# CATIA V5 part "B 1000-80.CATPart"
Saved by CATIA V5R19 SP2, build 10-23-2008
Part number: B 1000-80
Bounding box of the stored display mesh (mm): x -24.865 to 24.865, y -24.997 to 24.997, z 0 to 255
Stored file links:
  C:\Users\Bora\Desktop\3D Katı model\B serisi\B 1000\B 1000-80.CATPart
  C:\Program Files\Dassault Systemes\B19\intel_a\reffiles\standard\MetricThickPitch.txt
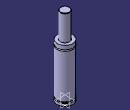
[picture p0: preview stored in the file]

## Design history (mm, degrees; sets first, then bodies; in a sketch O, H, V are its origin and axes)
Body1 (main body)
  Sketch1 on yz-plane, origin (0, 0, 0), H (0, 1, 0), V (0, 0, 1)
    point P1 (25, 159.5)
    point P2 (25, 155.5)
    point P3 (25, 159.5)
    point P6 (25, 155.5)
    point P9 (15, 254)
    point P11 (15, 254)
    arc A1 centre (25, 157.5) radius 2 from (25, 159.5) to (25, 155.5) ccw
    line L1 (25, 159.5) -> (25, 172)
    line L2 (25, 13) -> (25, 155.5)
    line L3 (21.5, 13) -> (21.5, 8)
    arc A2 centre (14, 254) radius 1 from (15, 254) to (14, 255) ccw
    line L4 (15, 254) -> (15, 172)
    line L5 (25, 0) -> (25, 8)
    line L6 (14, 255) -> (0, 255)
    point P15 (0, 255)
    line L7 (15, 172) -> (25, 172)
    line L8 (25, 0) -> (0, 0)
    line L9 (21.5, 13) -> (25, 13)
    line L10 (21.5, 8) -> (25, 8)
    coincidence: P15 V, P1 P3, P2 P6, P9 P11
    tangency: L6 A2
    horizontal: L7 H, L8 H, L9 H, L10 H
  Shaft1: profile Sketch1, axis Sketch1.V, angle 360
  Sketch2 on face of Shaft1 from Sketch1.L8, origin (0, 0, 0), H (1, 0, 0), V (0, -1, 0)
    point P1 (10, 0)
    distance P1 V = 10
  Hole1: placed by Sketch2, at (10, 0, 0) direction (0, 0, 1), diameter 6.647, depth 13, threaded "M8", thread diameter 8, thread depth 13, pitch 1.25
  CircPattern1: of Hole1, instances 2, angular step 180, axis from zx-plane
  CircPattern2: of CircPattern1, instances 2, angular step 180, axis from xy-plane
